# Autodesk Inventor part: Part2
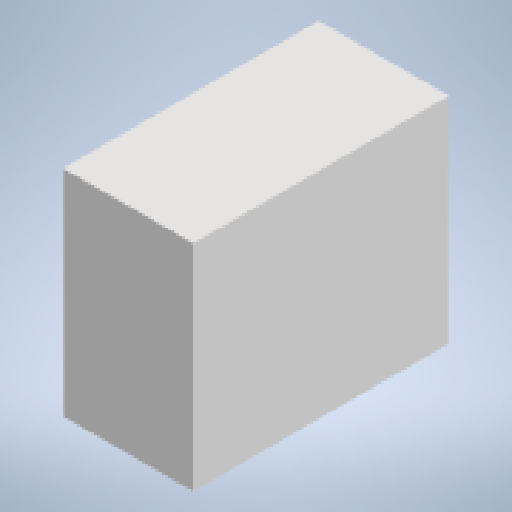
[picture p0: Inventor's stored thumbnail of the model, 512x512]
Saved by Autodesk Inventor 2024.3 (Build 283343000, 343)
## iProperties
Created: 2024-12
Part Number: Part2
Material: Generic
Document SubType Name: Modeling
Designer: ruhr
Density: 1 g/cm^3
Appearance: Default
Author: ruhr
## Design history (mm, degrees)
sketch "Sketch1"
  geometry: L1 (8.078, 9.446)-(-8.42, 9.446); L2 (-8.42, 9.446)-(-8.42, -10.207); L3 (-8.42, -10.207)-(8.078, -10.207); L4 (8.078, -10.207)-(8.078, 9.446); 1 further point
  constraints: 8 end point, 2 parallel, 1 horizontal, 1 perpendicular
extrude "Extrusion1" new body sketch "Sketch1" distance "d0" = 10; taper "d1" = 0 deg
body "Solid1"
